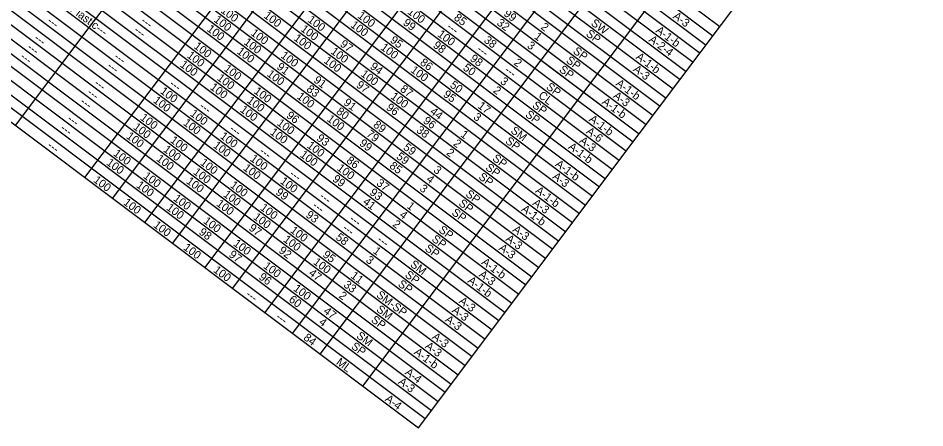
# Model space of a CAD drawing. Extents: x 627484.2 to 627517.5, y 367968.7 to 367996.9.
# Drawn here: x 627492.24 to 627498.36, y 367984.17 to 367986.94 of the extents above; entities that cross this region are included whole.
import ezdxf

# ---------------------------------------------------------------- set-up
doc = ezdxf.new("R2010")
doc.units = 0
doc.layers.add('Default', color=7, linetype='Continuous')

msp = doc.modelspace()

# ---------------------------------------------------------------- linework, layer by layer
at = {"layer": 'Default'}
for p, q in [((627491.735, 367990.8201), (627496.9779, 367986.8832)), ((627491.6882, 367990.7577), (627496.9311, 367986.8208)), ((627491.6413, 367990.6954), (627496.8842, 367986.7584)), ((627491.6003, 367990.6408), (627496.8433, 367986.7038)), ((627491.5535, 367990.5784), (627496.7964, 367986.6415)), ((627491.5067, 367990.516), (627496.7496, 367986.5791)), ((627491.4657, 367990.4615), (627496.7086, 367986.5245)), ((627491.4189, 367990.3991), (627496.6618, 367986.4621)), ((627491.372, 367990.3367), (627496.6149, 367986.3998)), ((627491.331, 367990.2821), (627496.5739, 367986.3452)), ((627491.2842, 367990.2198), (627496.5271, 367986.2828)), ((627491.2374, 367990.1574), (627496.4803, 367986.2204)), ((627491.1905, 367990.095), (627496.4334, 367986.1581)), ((627491.1495, 367990.0404), (627496.3925, 367986.1035)), ((627491.1027, 367989.9781), (627496.3456, 367986.0411)), ((627491.0559, 367989.9157), (627496.2988, 367985.9787)), ((627491.009, 367989.8533), (627496.2519, 367985.9164)), ((627490.9622, 367989.791), (627496.2051, 367985.854)), ((627490.9212, 367989.7364), (627496.1641, 367985.7994)), ((627490.8744, 367989.674), (627496.1173, 367985.7371)), ((627490.7866, 367989.5571), (627496.0295, 367985.6201)), ((627490.8275, 367989.6116), (627496.0705, 367985.6747)), ((627490.7397, 367989.4947), (627495.9826, 367985.5577)), ((627490.6929, 367989.4323), (627495.9358, 367985.4954)), ((627490.6461, 367989.3699), (627495.889, 367985.433)), ((627490.6051, 367989.3154), (627495.848, 367985.3784)), ((627495.3965, 367986.9367), (627497.2202, 367989.3654)), ((627490.5582, 367989.253), (627495.8011, 367985.316)), ((627490.5114, 367989.1906), (627495.7543, 367985.2537)), ((627495.5836, 367986.7962), (627497.4073, 367989.2249)), ((627495.7707, 367986.6557), (627497.6998, 367989.2247)), ((627490.4646, 367989.1282), (627495.7075, 367985.1913)), ((627490.4236, 367989.0737), (627495.6665, 367985.1367)), ((627490.3767, 367989.0113), (627495.6197, 367985.0743)), ((627490.3299, 367988.9489), (627495.5728, 367985.012)), ((627490.2831, 367988.8865), (627495.526, 367984.9496)), ((627490.2421, 367988.832), (627495.485, 367984.895)), ((627490.1953, 367988.7696), (627495.4382, 367984.8326)), ((627490.1484, 367988.7072), (627495.3913, 367984.7703)), ((627496.4334, 367986.1581), (627498.3625, 367988.727)), ((627490.1016, 367988.6449), (627495.3445, 367984.7079)), ((627490.0606, 367988.5903), (627495.3035, 367984.6533)), ((627490.0138, 367988.5279), (627495.2567, 367984.591)), ((627489.9669, 367988.4655), (627495.2098, 367984.5286)), ((627489.9201, 367988.4032), (627495.163, 367984.4662)), ((627489.8791, 367988.3486), (627495.122, 367984.4116)), ((627496.0592, 367986.4391), (627497.5111, 367988.3726)), ((627489.8323, 367988.2862), (627495.0752, 367984.3493)), ((627489.7854, 367988.2238), (627495.0283, 367984.2869)), ((627489.7445, 367988.1693), (627494.9874, 367984.2323)), ((627492.7172, 367986.8759), (627493.7124, 367988.2013)), ((627489.6976, 367988.1069), (627494.9405, 367984.1699)), ((627492.6873, 367985.8619), (627494.1802, 367987.85)), ((627492.8744, 367985.7214), (627494.3673, 367987.7095)), ((627493.0927, 367985.5575), (627494.5856, 367987.5456)), ((627493.2799, 367985.417), (627494.7728, 367987.4051)), ((627493.4982, 367985.253), (627494.9911, 367987.2412)), ((627493.6853, 367985.1125), (627495.1782, 367987.1006)), ((627493.9036, 367984.9486), (627495.3965, 367986.9367)), ((627492.2195, 367986.2132), (627492.7172, 367986.8759)), ((627494.0907, 367984.8081), (627495.5836, 367986.7962)), ((627494.2778, 367984.6676), (627495.7707, 367986.6557)), ((627495.7707, 367986.6557), (627496.4334, 367986.1581)), ((627494.5663, 367984.451), (627496.0592, 367986.4391)), ((627494.9405, 367984.1699), (627496.4334, 367986.1581))]:
    msp.add_line(p, q, dxfattribs=at)

# ---------------------------------------------------------------- texts
for s, p in [('---Non Plastic---', (627492.4006, 367987.128)), ('100', (627493.6008, 367986.9827)), ('100', (627494.8625, 367986.9741)), ('99', (627495.5127, 367986.9614)), ('---', (627492.4277, 367986.9125)), ('---', (627493.0614, 367986.9122)), ('100', (627493.554, 367986.9203)), ('100', (627493.8913, 367986.9474)), ('100', (627494.1877, 367986.9199)), ('100', (627494.5251, 367986.947)), ('99', (627494.8321, 367986.8994)), ('85', (627495.1761, 367986.9337)), ('32', (627495.4658, 367986.899)), ('SW', (627496.1017, 367986.897)), ('A-3', (627496.6562, 367986.944)), ('---', (627493.0146, 367986.8498)), ('100', (627493.5071, 367986.8579)), ('100', (627493.8035, 367986.8304)), ('100', (627494.1409, 367986.8576)), ('100', (627494.4783, 367986.8847)), ('---', (627495.1284, 367986.872)), ('2', (627495.7629, 367986.8711)), ('SP', (627496.0684, 367986.8245)), ('A-1-b', (627496.5398, 367986.8485)), ('---', (627492.3399, 367986.7956)), ('100', (627493.7567, 367986.7681)), ('100', (627494.0941, 367986.7952)), ('95', (627494.745, 367986.7819)), ('100', (627495.0652, 367986.8219)), ('38', (627495.3785, 367986.7817)), ('1', (627495.7186, 367986.8067)), ('A-2-4', (627496.4929, 367986.7862)), ('---', (627492.293, 367986.7332)), ('100', (627493.4193, 367986.741)), ('100', (627493.7099, 367986.7057)), ('100', (627494.3436, 367986.7053)), ('97', (627494.407, 367986.7553)), ('100', (627494.681, 367986.7324)), ('98', (627495.0353, 367986.7468)), ('---', (627495.3311, 367986.7198)), ('3', (627495.6705, 367986.7453)), ('SP', (627495.9806, 367986.7076)), ('---', (627492.2462, 367986.6708)), ('---', (627492.8799, 367986.6705)), ('100', (627493.3725, 367986.6786)), ('100', (627494.0062, 367986.6782)), ('100', (627494.2968, 367986.643)), ('98', (627495.2848, 367986.657)), ('SP', (627495.9337, 367986.6452)), ('A-1-b', (627496.4051, 367986.6692)), ('---', (627492.8331, 367986.6081)), ('100', (627493.3257, 367986.6162)), ('100', (627493.622, 367986.5888)), ('91', (627493.9785, 367986.6015)), ('94', (627494.6094, 367986.6033)), ('100', (627494.8837, 367986.5802)), ('86', (627494.9469, 367986.6303)), ('50', (627495.2373, 367986.5951)), ('2', (627495.5814, 367986.6294)), ('SP', (627495.8869, 367986.5829)), ('A-3', (627496.3869, 367986.5854)), ('100', (627493.5752, 367986.5264)), ('100', (627493.9126, 367986.5535)), ('100', (627494.5463, 367986.5531)), ('---', (627495.5182, 367986.5792)), ('---', (627492.7453, 367986.4912)), ('---', (627493.2542, 367986.487)), ('100', (627493.5284, 367986.464)), ('91', (627494.228, 367986.5117)), ('97', (627494.516, 367986.4783)), ('50', (627495.1495, 367986.4782)), ('3', (627495.489, 367986.5036)), ('SP', (627495.7991, 367986.4659)), ('A-1-b', (627496.2705, 367986.4899)), ('---', (627492.6985, 367986.4288)), ('100', (627493.191, 367986.4369)), ('100', (627493.8247, 367986.4365)), ('100', (627494.1153, 367986.4013)), ('83', (627494.1799, 367986.4503)), ('100', (627494.749, 367986.4009)), ('87', (627494.8124, 367986.4508)), ('95', (627495.1036, 367986.4151)), ('2', (627495.4409, 367986.4423)), ('CL', (627495.7464, 367986.4079)), ('A-3', (627496.2523, 367986.406)), ('---', (627492.6516, 367986.3664)), ('100', (627493.1442, 367986.3745)), ('100', (627493.7779, 367986.3742)), ('91', (627494.4307, 367986.3595)), ('17', (627495.3369, 367986.3374)), ('SP', (627495.7054, 367986.3412)), ('A-1-b', (627496.1768, 367986.3652)), ('100', (627493.3937, 367986.2847)), ('---', (627493.4569, 367986.3347)), ('100', (627493.7311, 367986.3118)), ('96', (627494.0438, 367986.2721)), ('80', (627494.3811, 367986.2992)), ('96', (627494.7185, 367986.3263)), ('44', (627495.0148, 367986.2989)), ('SP', (627495.6586, 367986.2788)), ('---', (627492.5638, 367986.2495)), ('100', (627493.0563, 367986.2576)), ('100', (627493.3469, 367986.2223)), ('100', (627493.9806, 367986.2219)), ('100', (627494.318, 367986.2491)), ('89', (627494.6308, 367986.2092)), ('96', (627494.9681, 367986.2364)), ('3', (627495.3076, 367986.2619)), ('A-1-b', (627496.089, 367986.2482)), ('---', (627492.517, 367986.1871)), ('100', (627493.0095, 367986.1952)), ('---', (627493.6597, 367986.1825)), ('100', (627493.9338, 367986.1596)), ('79', (627494.584, 367986.1468)), ('38', (627494.9219, 367986.1736)), ('SM', (627495.5595, 367986.1703)), ('A-6', (627496.0693, 367986.1654)), ('100', (627492.9627, 367986.1328)), ('100', (627493.2591, 367986.1054)), ('100', (627493.5964, 367986.1325)), ('93', (627494.248, 367986.1187)), ('1', (627495.221, 367986.144)), ('SP', (627495.5239, 367986.0995)), ('A-3', (627496.0239, 367986.102)), ('---', (627492.4291, 367986.0701)), ('100', (627493.2122, 367986.043)), ('100', (627493.5496, 367986.0701)), ('100', (627494.1833, 367986.0697)), ('99', (627494.5372, 367986.0845)), ('59', (627494.8336, 367986.057)), ('2', (627495.1715, 367986.0836)), ('A-1-b', (627495.9485, 367986.0611)), ('100', (627492.8749, 367986.0159)), ('100', (627493.1654, 367985.9806)), ('100', (627493.7991, 367985.9803)), ('---', (627493.8624, 367986.0303)), ('100', (627494.1365, 367986.0074)), ('86', (627494.4492, 367985.9676)), ('59', (627494.7867, 367985.9946)), ('2', (627495.1247, 367986.0213)), ('SP', (627495.4361, 367985.9825)), ('100', (627492.828, 367985.9535)), ('100', (627493.4618, 367985.9531)), ('100', (627493.7523, 367985.9179)), ('100', (627494.386, 367985.9175)), ('85', (627494.7406, 367985.9317)), ('3', (627495.0382, 367985.9033)), ('SP', (627495.3893, 367985.9201)), ('A-1-b', (627495.8607, 367985.9441)), ('100', (627493.0776, 367985.8637)), ('100', (627493.4149, 367985.8908)), ('---', (627494.0651, 367985.8781)), ('99', (627494.3557, 367985.8428)), ('SP', (627495.3424, 367985.8578)), ('A-3', (627495.8424, 367985.8603)), ('100', (627492.7402, 367985.8366)), ('100', (627493.0307, 367985.8013)), ('100', (627493.3681, 367985.8284)), ('100', (627493.6645, 367985.8009)), ('100', (627494.0018, 367985.828)), ('37', (627494.6521, 367985.8152)), ('4', (627494.9898, 367985.8421)), ('100', (627493.6176, 367985.7386)), ('99', (627493.9715, 367985.7533)), ('93', (627494.6065, 367985.7519)), ('3', (627494.9446, 367985.7785)), ('SP', (627495.2546, 367985.7408)), ('A-1-b', (627495.726, 367985.7648)), ('100', (627492.9429, 367985.6843)), ('100', (627493.2803, 367985.7115)), ('100', (627493.5708, 367985.6762)), ('---', (627494.2678, 367985.7259)), ('41', (627494.561, 367985.6886)), ('SP', (627495.2078, 367985.6784)), ('A-3', (627495.7078, 367985.681)), ('100', (627493.2334, 367985.6491)), ('100', (627493.8672, 367985.6487)), ('93', (627494.1755, 367985.6001)), ('---', (627494.221, 367985.6635)), ('1', (627494.858, 367985.6606)), ('SP', (627495.1609, 367985.6161)), ('A-1-b', (627495.6323, 367985.6401)), ('100', (627493.483, 367985.5592)), ('100', (627493.8204, 367985.5863)), ('---', (627494.4705, 367985.5737)), ('2', (627494.7617, 367985.5379)), ('4', (627494.8083, 367985.6004)), ('100', (627493.1456, 367985.5321)), ('98', (627493.4531, 367985.4841)), ('97', (627493.7901, 367985.5115)), ('100', (627494.0699, 367985.4965)), ('---', (627494.4237, 367985.5113)), ('SP', (627495.0731, 367985.4991)), ('A-3', (627495.5731, 367985.5016)), ('100', (627494.0231, 367985.4341)), ('58', (627494.3774, 367985.4485)), ('---', (627494.6576, 367985.4331)), ('SP', (627495.0263, 367985.4368)), ('A-3', (627495.5263, 367985.4393)), ('100', (627493.3483, 367985.3799)), ('100', (627493.6857, 367985.407)), ('92', (627493.9927, 367985.3594)), ('1', (627494.6297, 367985.3566)), ('SP', (627494.9794, 367985.3744)), ('A-3', (627495.4795, 367985.3769)), ('97', (627493.6554, 367985.3322)), ('95', (627494.2898, 367985.3313)), ('3', (627494.5816, 367985.2952)), ('100', (627493.8884, 367985.2548)), ('100', (627494.2258, 367985.2819)), ('SM', (627494.8804, 367985.2659)), ('A-1-b', (627495.363, 367985.2814)), ('100', (627493.551, 367985.2277)), ('96', (627493.8579, 367985.1802)), ('47', (627494.1955, 367985.2071)), ('11', (627494.4788, 367985.1894)), ('SP', (627494.8448, 367985.1951)), ('A-3', (627495.3448, 367985.1976)), ('33', (627494.4307, 367985.128)), ('SP', (627494.798, 367985.1327)), ('A-1-b', (627495.2693, 367985.1567)), ('100', (627494.0911, 367985.1026)), ('2', (627494.3987, 367985.0545)), ('SM-SP', (627494.6524, 367985.0591)), ('---', (627493.7702, 367985.0632)), ('60', (627494.0605, 367985.028)), ('A-3', (627495.2101, 367985.0183)), ('47', (627494.2948, 367984.9496)), ('SM', (627494.652, 367984.9618)), ('A-3', (627495.1633, 367984.9559)), ('---', (627493.9729, 367984.9109)), ('4', (627494.2639, 367984.8753)), ('SP', (627494.6165, 367984.891)), ('A-3', (627495.1165, 367984.8935)), ('84', (627494.1598, 367984.7706)), ('SM', (627494.5174, 367984.7825)), ('A-3', (627495.0287, 367984.7766)), ('SP', (627494.4818, 367984.7117)), ('A-3', (627494.9818, 367984.7142)), ('A-1-b', (627494.9064, 367984.6733)), ('ML', (627494.3809, 367984.6045)), ('A-4', (627494.8456, 367984.5361)), ('A-3', (627494.8003, 367984.4725)), ('A-4', (627494.7109, 367984.3567))]:
    msp.add_text(s, height=0.055, rotation=323.09678, dxfattribs=at).set_placement(p)

doc.saveas('drawing.dxf')
